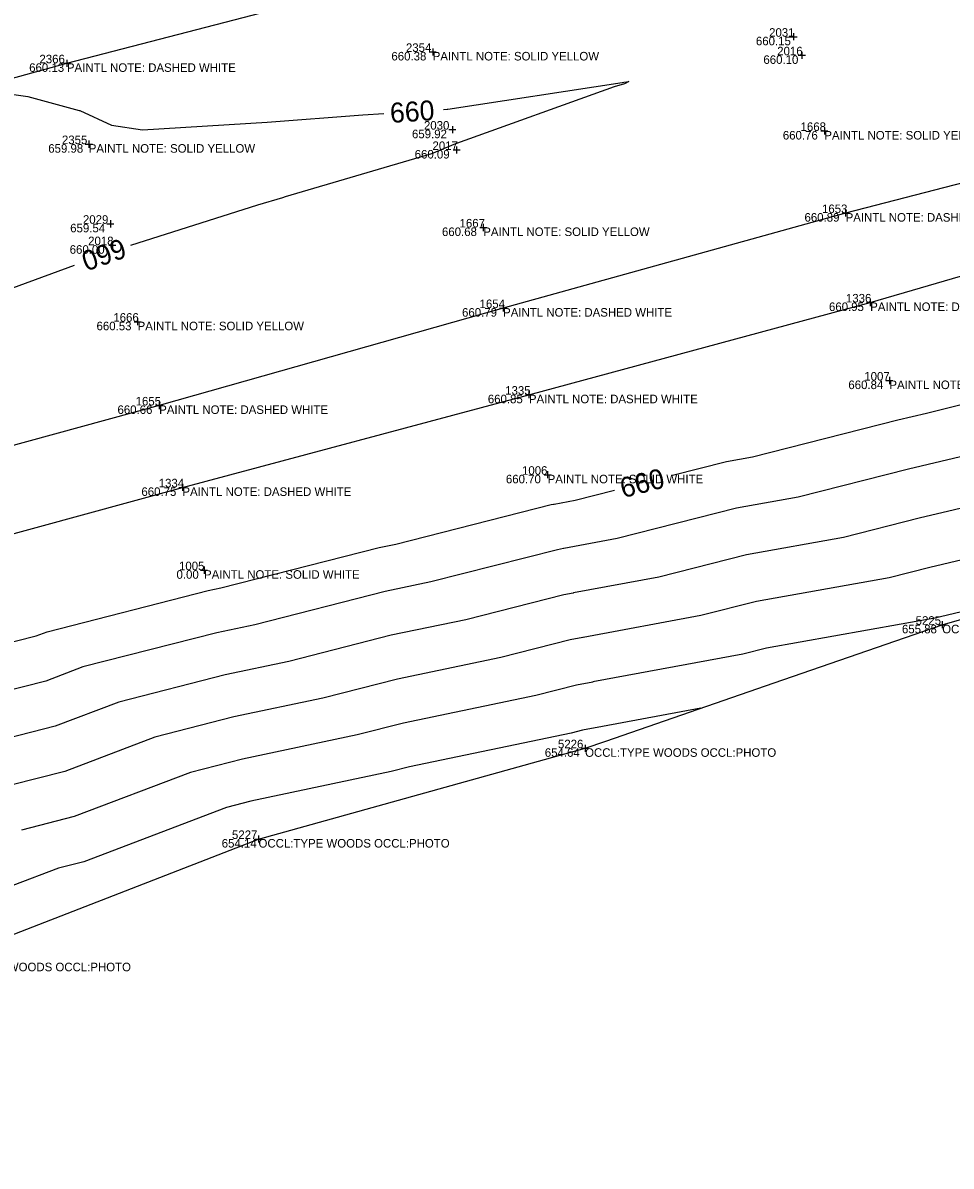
# Model space of a CAD drawing. Extents: x 2129350 to 2137777, y 657588 to 659885.
# Drawn here: x 2129934.4 to 2130064.8, y 657699 to 657859.5 of the extents above; entities that cross this region are included whole.
import ezdxf

# ---------------------------------------------------------------- set-up
doc = ezdxf.new("R2010")
doc.units = 0
for name, color, linetype in [('DT_X_Contour_Major', 7, 'Continuous'), ('DT_X_Contour_Minor', 7, 'Continuous'), ('DT_X_TIN_Hull', 7, 'Continuous'), ('PV_X_COP', 7, 'Continuous'), ('SV_X_Shot_Marker', 7, 'Continuous'), ('SV_X_Text_Comment', 7, 'Continuous'), ('SV_X_Text_Elevation', 7, 'Continuous'), ('SV_X_Text_Name', 7, 'Continuous')]:
    doc.layers.add(name, color=color, linetype=linetype)

msp = doc.modelspace()

# ---------------------------------------------------------------- linework, layer by layer
at = {"layer": 'DT_X_Contour_Major'}
for points in [[(2129922.13, 657870.29), (2129912.62, 657861.92), (2129907.16, 657857.06), (2129914.76, 657853.86), (2129927.56, 657850.23), (2129935.11, 657849.15), (2129942.35, 657847.22), (2129942.4, 657847.21), (2129942.41, 657847.21), (2129946.89, 657845.16), (2129951.24, 657844.51), (2129968.75, 657845.57), (2129982.15, 657846.59), (2129985.13, 657846.79)], [(2129993.51, 657847.36), (2129994.01, 657847.39), (2129994.09, 657847.4), (2130018.6, 657851.12), (2130018.84, 657851.16), (2130019.52, 657851.26), (2130018.9, 657850.93), (2130017.48, 657850.53), (2129995.34, 657842.57), (2129995.16, 657842.52), (2129991.83, 657841.13), (2129971.24, 657835.06), (2129970.9, 657834.94), (2129967.36, 657833.92), (2129949.56, 657828.26)], [(2129941.65, 657825.44), (2129923.75, 657818.91), (2129916.28, 657816.05), (2129900.58, 657810.27), (2129885.03, 657803.24), (2129877.76, 657799.89), (2129864.56, 657793.99), (2129855.88, 657785.35), (2129855.81, 657785.28), (2129852.77, 657782.18)], [(2130025.67, 657796), (2130033.24, 657797.93), (2130036.88, 657798.58), (2130057.31, 657803.76), (2130061.34, 657804.72), (2130081.53, 657809.77), (2130086.05, 657810.85), (2130105.77, 657815.78), (2130106.34, 657815.93), (2130106.61, 657816), (2130122.71, 657820.14)], [(2129920.6, 657769.46), (2129936.31, 657773.44), (2129937.83, 657774.02), (2129960.45, 657779.8), (2129962.21, 657780.17), (2129984.45, 657785.84), (2129986.78, 657786.32), (2130008.62, 657791.88), (2130008.95, 657791.94), (2130009.02, 657791.95), (2130011.99, 657792.5), (2130017.53, 657793.92)], [(2130029.62, 657763.28), (2130015.84, 657760.72), (2130015.84, 657760.72), (2130013.03, 657760.2), (2130011.41, 657759.79), (2129988.73, 657755.04), (2129986.14, 657754.38), (2129966.44, 657750.22), (2129963.01, 657749.34), (2129942.99, 657741.71), (2129939.42, 657740.81), (2129933.03, 657738.38)]]:
    msp.add_lwpolyline(points, dxfattribs=at)
at = {"layer": 'DT_X_Contour_Minor'}
for points in [[(2130067.87, 657799.01), (2130058.81, 657796.86), (2130043.28, 657792.91), (2130034.65, 657791.38), (2130017.87, 657787.1), (2130010.38, 657785.71), (2130010.33, 657785.69), (2130009.51, 657785.54), (2129991.71, 657781.02), (2129985.3, 657779.68), (2129967, 657775.01), (2129961.65, 657773.88), (2129942.86, 657769.08), (2129937.65, 657767.1), (2129918.58, 657762.26)], [(2130074.4, 657793.3), (2130060.3, 657789.95), (2130049.68, 657787.25), (2130036.05, 657784.82), (2130023.75, 657781.69), (2130011.75, 657779.46), (2130011.71, 657779.45), (2130010.39, 657779.2), (2129996.63, 657775.71), (2129986.16, 657773.52), (2129971.78, 657769.85), (2129962.85, 657767.97), (2129947.9, 657764.15), (2129938.98, 657760.75), (2129923.79, 657756.9)], [(2130080.92, 657787.6), (2130061.79, 657783.04), (2130056.08, 657781.59), (2130037.46, 657778.27), (2130029.64, 657776.28), (2130013.11, 657773.21), (2130013.08, 657773.21), (2130011.27, 657772.87), (2130001.56, 657770.4), (2129987.02, 657767.36), (2129976.57, 657764.69), (2129964.05, 657762.05), (2129952.94, 657759.21), (2129940.32, 657754.4), (2129929, 657751.53)], [(2130087.45, 657781.89), (2130063.29, 657776.13), (2130062.48, 657775.93), (2130038.86, 657771.72), (2130035.52, 657770.87), (2130014.48, 657766.97), (2130014.46, 657766.96), (2130012.15, 657766.53), (2130006.48, 657765.09), (2129987.87, 657761.2), (2129981.35, 657759.53), (2129965.25, 657756.13), (2129957.97, 657754.28), (2129941.65, 657748.06), (2129934.21, 657746.17)]]:
    msp.add_lwpolyline(points, dxfattribs=at)
at = {"layer": 'DT_X_TIN_Hull'}
msp.add_lwpolyline([(2129695.67, 657810.93), (2129698.82, 657799.5), (2129700.33, 657786.76), (2129705.34, 657764.51), (2129708.77, 657762.64), (2129709.61, 657751.16), (2129712.26, 657739.41), (2129715.61, 657727.9), (2129719.1, 657716.22), (2129743.16, 657723.01), (2129835.52, 657698.99), (2129843.59, 657711.65), (2129872.09, 657720.5), (2129922.77, 657727.54), (2129967.52, 657744.92), (2130013.38, 657757.66), (2130016.29, 657758.67), (2130039.91, 657766.83), (2130063.53, 657775), (2130087.48, 657781.86)], dxfattribs=at)
at = {"layer": 'PV_X_COP'}
for points in [[(2129700.33, 657786.76), (2129747.53, 657800.34), (2129796.29, 657813.57), (2129844.17, 657826.94), (2129892.3, 657840.51), (2129940.61, 657853.83), (2129988.87, 657866.4), (2130037.09, 657880.45), (2130085.21, 657893.8)], [(2130098.51, 657845.32), (2130049.97, 657832.8), (2130001.87, 657819.46), (2129953.57, 657805.79), (2129905.5, 657792.62), (2129857.29, 657780.21), (2129809.09, 657766.1), (2129760.73, 657752.96), (2129712.27, 657739.41)], [(2129715.61, 657727.9), (2129763.96, 657741.55), (2129812.15, 657754.53), (2129860.53, 657767.7), (2129908.69, 657781.1), (2129956.83, 657794.29), (2130005.49, 657807.3), (2130053.42, 657820.25), (2130101.43, 657834.24)]]:
    msp.add_lwpolyline(points, dxfattribs=at)
at = {"layer": 'SV_X_Shot_Marker'}
for p, q in [((2130042.67, 657858.06), (2130042.67, 657857.06)), ((2130042.17, 657857.56), (2130043.17, 657857.56)), ((2130042.67, 657857.56), (2130042.67, 657857.56)), ((2129991.48, 657855.43), (2129992.48, 657855.43)), ((2129991.98, 657855.93), (2129991.98, 657854.93)), ((2129991.98, 657855.43), (2129991.98, 657855.43)), ((2130043.32, 657854.95), (2130044.32, 657854.95)), ((2130043.82, 657855.45), (2130043.82, 657854.45)), ((2130043.82, 657854.95), (2130043.82, 657854.95)), ((2129940.11, 657853.83), (2129941.11, 657853.83)), ((2129940.61, 657854.33), (2129940.61, 657853.33)), ((2129940.61, 657853.83), (2129940.61, 657853.83)), ((2129994.74, 657845.02), (2129994.74, 657844.02)), ((2129994.24, 657844.52), (2129995.24, 657844.52)), ((2129994.74, 657844.52), (2129994.74, 657844.52)), ((2130046.48, 657844.33), (2130047.48, 657844.33)), ((2130046.98, 657844.83), (2130046.98, 657843.83)), ((2130046.98, 657844.33), (2130046.98, 657844.33)), ((2129943.18, 657842.48), (2129944.18, 657842.48)), ((2129943.68, 657842.98), (2129943.68, 657841.98)), ((2129943.68, 657842.48), (2129943.68, 657842.48)), ((2129995.34, 657842.16), (2129995.34, 657841.16)), ((2129994.84, 657841.66), (2129995.84, 657841.66)), ((2129995.34, 657841.66), (2129995.34, 657841.66)), ((2130049.47, 657832.8), (2130050.47, 657832.8)), ((2130049.97, 657833.3), (2130049.97, 657832.3)), ((2130049.97, 657832.8), (2130049.97, 657832.8)), ((2129946.22, 657831.3), (2129947.22, 657831.3)), ((2129946.72, 657831.8), (2129946.72, 657830.8)), ((2129946.72, 657831.3), (2129946.72, 657831.3)), ((2129998.58, 657830.78), (2129999.58, 657830.78)), ((2129999.08, 657831.28), (2129999.08, 657830.28)), ((2129999.08, 657830.78), (2129999.08, 657830.78)), ((2129946.49, 657828.29), (2129947.49, 657828.29)), ((2129946.99, 657828.79), (2129946.99, 657827.79)), ((2129946.99, 657828.29), (2129946.99, 657828.29)), ((2130001.37, 657819.46), (2130002.37, 657819.46)), ((2130001.87, 657819.96), (2130001.87, 657818.96)), ((2130001.87, 657819.46), (2130001.87, 657819.46)), ((2130052.92, 657820.25), (2130053.92, 657820.25)), ((2130053.42, 657820.75), (2130053.42, 657819.75)), ((2130053.42, 657820.25), (2130053.42, 657820.25)), ((2129950.54, 657818.05), (2129950.54, 657817.05)), ((2129950.04, 657817.55), (2129951.04, 657817.55)), ((2129950.54, 657817.55), (2129950.54, 657817.55)), ((2130056.12, 657809.79), (2130056.12, 657808.79)), ((2130055.62, 657809.29), (2130056.62, 657809.29)), ((2130056.12, 657809.29), (2130056.12, 657809.29)), ((2130004.99, 657807.3), (2130005.99, 657807.3)), ((2130005.49, 657807.8), (2130005.49, 657806.8)), ((2130005.49, 657807.3), (2130005.49, 657807.3)), ((2129953.07, 657805.79), (2129954.07, 657805.79)), ((2129953.57, 657806.29), (2129953.57, 657805.29)), ((2129953.57, 657805.79), (2129953.57, 657805.79)), ((2130007.62, 657796.06), (2130008.62, 657796.06)), ((2130008.12, 657796.56), (2130008.12, 657795.56)), ((2130008.12, 657796.06), (2130008.12, 657796.06)), ((2129956.33, 657794.29), (2129957.33, 657794.29)), ((2129956.83, 657794.79), (2129956.83, 657793.79)), ((2129956.83, 657794.29), (2129956.83, 657794.29)), ((2129959.37, 657782.66), (2129960.37, 657782.66)), ((2129959.87, 657783.16), (2129959.87, 657782.16)), ((2129959.87, 657782.66), (2129959.87, 657782.66)), ((2130063.03, 657775), (2130064.03, 657775)), ((2130063.53, 657775.5), (2130063.53, 657774.5)), ((2130063.53, 657775), (2130063.53, 657775)), ((2130012.88, 657757.66), (2130013.88, 657757.66)), ((2130013.38, 657758.16), (2130013.38, 657757.16)), ((2130013.38, 657757.66), (2130013.38, 657757.66)), ((2129967.52, 657745.42), (2129967.52, 657744.42)), ((2129967.02, 657744.92), (2129968.02, 657744.92)), ((2129967.52, 657744.92), (2129967.52, 657744.92))]:
    msp.add_line(p, q, dxfattribs=at)

# ---------------------------------------------------------------- texts
at = {"layer": 'DT_X_Contour_Major'}
for rotation, p in [(3.8557, (2129986.07, 657845.45)), (199.5524, (2129948.28, 657829.33)), (14.3106, (2130018.7, 657792.77))]:
    msp.add_text('660', height=2.8, rotation=rotation, dxfattribs=at).set_placement(p)
at = {"layer": 'SV_X_Text_Comment'}
for s, p in [('PAINTL NOTE: SOLID YELLOW', (2129991.98, 657854.23)), ('PAINTL NOTE: DASHED WHITE', (2129940.61, 657852.63)), ('PAINTL NOTE: SOLID YELLOW', (2130046.98, 657843.13)), ('PAINTL NOTE: SOLID YELLOW', (2129943.68, 657841.28)), ('PAINTL NOTE: DASHED WHITE', (2130049.97, 657831.6)), ('PAINTL NOTE: SOLID YELLOW', (2129999.08, 657829.58)), ('PAINTL NOTE: DASHED WHITE', (2130001.87, 657818.26)), ('PAINTL NOTE: DASHED WHITE', (2130053.42, 657819.05)), ('PAINTL NOTE: SOLID YELLOW', (2129950.54, 657816.35)), ('PAINTL NOTE: SOLID WHITE', (2130056.12, 657808.09)), ('PAINTL NOTE: DASHED WHITE', (2130005.49, 657806.1)), ('PAINTL NOTE: DASHED WHITE', (2129953.57, 657804.6)), ('PAINTL NOTE: SOLID WHITE', (2130008.12, 657794.86)), ('PAINTL NOTE: DASHED WHITE', (2129956.83, 657793.09)), ('PAINTL NOTE: SOLID WHITE', (2129959.87, 657781.46)), ('OCCL:TYPE WOODS OCCL:PHOTO', (2130063.53, 657773.8)), ('OCCL:TYPE WOODS OCCL:PHOTO', (2130013.38, 657756.46)), ('OCCL:TYPE WOODS OCCL:PHOTO', (2129967.52, 657743.72)), ('OCCL:TYPE WOODS OCCL:PHOTO', (2129922.77, 657726.35))]:
    msp.add_text(s, height=1.2, dxfattribs=at).set_placement(p)
at = {"layer": 'SV_X_Text_Elevation'}
for s, p in [('660.15', (2130037.37, 657856.36)), ('660.38', (2129986.18, 657854.23)), ('660.10', (2130038.42, 657853.75)), ('660.13', (2129935.31, 657852.63)), ('659.92', (2129989.07, 657843.31)), ('660.76', (2130041.15, 657843.13)), ('659.98', (2129937.99, 657841.28)), ('660.09', (2129989.45, 657840.46)), ('660.89', (2130044.19, 657831.6)), ('659.54', (2129941.07, 657830.1)), ('660.68', (2129993.28, 657829.58)), ('660.00', (2129941, 657827.09)), ('660.79', (2129996.1, 657818.26)), ('660.95', (2130047.63, 657819.05)), ('660.53', (2129944.77, 657816.35)), ('660.84', (2130050.35, 657808.09)), ('660.85', (2129999.72, 657806.1)), ('660.66', (2129947.71, 657804.6)), ('660.70', (2130002.26, 657794.86)), ('660.75', (2129951.07, 657793.09)), ('0.00', (2129956, 657781.46)), ('655.88', (2130057.88, 657773.8)), ('654.64', (2130007.72, 657756.46)), ('654.14', (2129962.35, 657743.72))]:
    msp.add_text(s, height=1.2, dxfattribs=at).set_placement(p)
at = {"layer": 'SV_X_Text_Name'}
for s, p in [('2031', (2130039.22, 657857.56)), ('2354', (2129988.22, 657855.43)), ('2016', (2130040.36, 657854.95)), ('2366', (2129936.75, 657853.83)), ('2030', (2129990.75, 657844.52)), ('1668', (2130043.64, 657844.33)), ('2355', (2129939.91, 657842.48)), ('2017', (2129991.95, 657841.66)), ('1653', (2130046.65, 657832.8)), ('2029', (2129942.86, 657831.3)), ('1667', (2129995.75, 657830.78)), ('2018', (2129943.59, 657828.29)), ('1336', (2130050.01, 657820.25)), ('1654', (2129998.56, 657819.46)), ('1666', (2129947.13, 657817.55)), ('1007', (2130052.59, 657809.29)), ('1335', (2130002.16, 657807.3)), ('1655', (2129950.26, 657805.79)), ('1006', (2130004.52, 657796.06)), ('1334', (2129953.5, 657794.29)), ('1005', (2129956.35, 657782.66)), ('5225', (2130059.8, 657775)), ('5226', (2130009.57, 657757.66)), ('5227', (2129963.79, 657744.92))]:
    msp.add_text(s, height=1.2, dxfattribs=at).set_placement(p)

doc.saveas('drawing.dxf')
